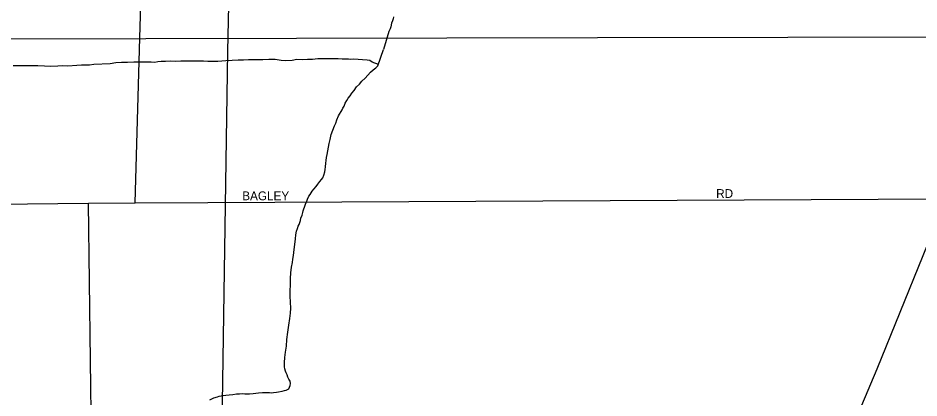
# Model space of a CAD drawing. Extents: x 2010165 to 2382125, y 1060529 to 1407316.
# Drawn here: x 2126446 to 2131582, y 1228053 to 1230221 of the extents above; entities that cross this region are included whole.
import ezdxf

# ---------------------------------------------------------------- set-up
doc = ezdxf.new("R2010")
doc.units = 0
for name, color, linetype in [('GM_X_City_Street', 7, 'Continuous'), ('GM_X_City_Street_Text', 7, 'Continuous'), ('GM_X_Corporation', 7, 'Continuous'), ('GM_X_County_Road', 7, 'Continuous'), ('GM_X_Minor_River', 7, 'Continuous'), ('GM_X_Rail_Line', 7, 'Continuous'), ('GM_X_Township_Subdivision', 7, 'Continuous')]:
    doc.layers.add(name, color=color, linetype=linetype)

msp = doc.modelspace()

# ---------------------------------------------------------------- linework, layer by layer
at = {"layer": 'GM_X_City_Street'}
for points in [[(2127528.7, 1229168.7), (2131731.9, 1229190.2)], [(2131133.5, 1227718.6), (2131344.2, 1228219.6), (2131737.3, 1229190.2)]]:
    msp.add_lwpolyline(points, dxfattribs=at)
at = {"layer": 'GM_X_Corporation'}
msp.add_lwpolyline([(2131636.8, 1226885.6), (2131550.4, 1226943.1), (2131486.1, 1226996.8), (2131429.8, 1227048.5), (2131401.6, 1227074.4), (2131379.2, 1227134.4), (2131352.4, 1227258.4), (2131342.1, 1227310.5), (2131343.7, 1227374.6), (2131363.2, 1227453), (2131396.7, 1227523.3), (2131430.3, 1227587.7), (2131468, 1227632.1), (2131573.5, 1227709), (2127608.1, 1227775.4), (2127641.5, 1230030.5), (2127699.3, 1232671.6), (2128286.9, 1232638.9), (2128858.2, 1232617.9), (2130176.4, 1232600.5), (2130656, 1232568.1), (2130665.6, 1232672.5), (2131903.1, 1232704.3)], dxfattribs=at)
at = {"layer": 'GM_X_County_Road'}
for points in [[(2127141, 1230108), (2127168.7, 1231058), (2127179.2, 1231416.5), (2127217.3, 1232723)], [(2127113.5, 1229166.6), (2127141, 1230108), (2127141, 1230108)], [(2121105.1, 1229101.1), (2126848.1, 1229163.7), (2127113.5, 1229166.6), (2127528.7, 1229168.7)]]:
    msp.add_lwpolyline(points, dxfattribs=at)
at = {"layer": 'GM_X_Minor_River'}
for points in [[(2128587.4, 1230227.7), (2128585.4, 1230215.6), (2128581.4, 1230205.6), (2128575.5, 1230191.6), (2128571.5, 1230171.5), (2128567.5, 1230159.4), (2128559.6, 1230143.3), (2128529, 1230040.7)], [(2128320.3, 1229751.1), (2128328.2, 1229763.2), (2128340, 1229777.4), (2128349.8, 1229791.6), (2128361.6, 1229807.9), (2128375.3, 1229828.1), (2128393.1, 1229844.4), (2128406.9, 1229860.7), (2128424.8, 1229877), (2128440.5, 1229895.3), (2128456.3, 1229911.6), (2128470.2, 1229925.8), (2128486.1, 1229936.1), (2128497.9, 1229948.3), (2128529, 1230040.7)], [(2128500.2, 1229955.1), (2128465.5, 1229969.9), (2128451.4, 1229977.8), (2128437.3, 1229979.5), (2128359, 1229986.4), (2128343, 1229984.2), (2128330.9, 1229986), (2128318.9, 1229985.8), (2128294.8, 1229985.5), (2128270.8, 1229987.1), (2128242.7, 1229988.8), (2128212.6, 1229988.3), (2128184.5, 1229987.9), (2128154.4, 1229987.5), (2128124.4, 1229985), (2128096.3, 1229984.6), (2128068.3, 1229982.2), (2128036.2, 1229983.7), (2128008.2, 1229979.3), (2127972.1, 1229976.8), (2127946, 1229978.4), (2127911.9, 1229983.9), (2127875.8, 1229983.4), (2127841.7, 1229982.9), (2127813.6, 1229982.5), (2127787.6, 1229982.1), (2127759.5, 1229981.7), (2127731.4, 1229981.3), (2127701.4, 1229980.8), (2127667.3, 1229978.3), (2127631.2, 1229975.8), (2127585.2, 1229973.1), (2127555.1, 1229972.7), (2127529, 1229972.3), (2127502.9, 1229973.9), (2127474.8, 1229975.5), (2127442.8, 1229975.1), (2127406.7, 1229974.5), (2127374.6, 1229974.1), (2127344.5, 1229973.6), (2127314.4, 1229975.2), (2127286.4, 1229972.8), (2127262.3, 1229972.4), (2127242.3, 1229970.1), (2127226.3, 1229967.9), (2127204.2, 1229969.6), (2127176.1, 1229969.2), (2127142.1, 1229968.7), (2127106, 1229968.1), (2127069.9, 1229967.6), (2127035.8, 1229967.1), (2127003.8, 1229964.6), (2126971.7, 1229960.2), (2126877.6, 1229954.8), (2126853.5, 1229952.4), (2126831.5, 1229952.1), (2126807.4, 1229951.8), (2126781.4, 1229949.4), (2126729.3, 1229946.6), (2126701.2, 1229948.2), (2126673.2, 1229945.8), (2126631.1, 1229945.2), (2126597, 1229946.7), (2126558.8, 1229948.1), (2126522.7, 1229947.6), (2126418.5, 1229948.1)], [(2127648.9, 1228071.7), (2127670.9, 1228074), (2127690.9, 1228076.3), (2127709, 1228076.6), (2127725, 1228078.8), (2127739, 1228077), (2127765.1, 1228077.4), (2127787.1, 1228079.7), (2127817.2, 1228082.2), (2127839.2, 1228084.5), (2127859.2, 1228084.8), (2127879.3, 1228085.1), (2127889.3, 1228083.2), (2127903.3, 1228085.4), (2127919.4, 1228085.6), (2127931.4, 1228087.8), (2127951.4, 1228092.1), (2127965.4, 1228096.4), (2127975.4, 1228098.5), (2127989.3, 1228104.7), (2127993.2, 1228114.8), (2127997, 1228124.9), (2127998.9, 1228135), (2127996.7, 1228149), (2127990.5, 1228160.9), (2127984.3, 1228172.9), (2127980.1, 1228184.9), (2127973.9, 1228196.8), (2127971.8, 1228206.8), (2127967.6, 1228218.8), (2127965.4, 1228230.8), (2127965.1, 1228254.9), (2127966.6, 1228285), (2127970.2, 1228315.2), (2127975.7, 1228349.4), (2127979.2, 1228387.5), (2127984.6, 1228427.8), (2127990, 1228468), (2127995.5, 1228506.2), (2127999.1, 1228536.3), (2128000.6, 1228566.4), (2128000.1, 1228600.6), (2127997.6, 1228634.6), (2127997.2, 1228664.7), (2127998.7, 1228698.9), (2128000.2, 1228735), (2128001.7, 1228767.1), (2128005.3, 1228799.3), (2128010.9, 1228825.5), (2128012.6, 1228845.6), (2128016.3, 1228865.7), (2128018.1, 1228883.8), (2128027, 1228960.2), (2128030.7, 1228984.3), (2128034.4, 1229004.4), (2128040.2, 1229020.6), (2128044, 1229032.6), (2128047.9, 1229042.7), (2128051.7, 1229054.8), (2128055.6, 1229064.9), (2128057.4, 1229079), (2128065.1, 1229095.2), (2128068.9, 1229111.3), (2128070.8, 1229121.3), (2128074.6, 1229131.4), (2128078.5, 1229141.5), (2128084.3, 1229159.7), (2128092, 1229175.8), (2128095.9, 1229187.9), (2128103.7, 1229204.1), (2128111.5, 1229214.2), (2128123.3, 1229232.5), (2128133.2, 1229244.6), (2128145, 1229258.9), (2128154.8, 1229273.1), (2128166.6, 1229287.3), (2128176.5, 1229299.5), (2128184.3, 1229309.6), (2128190.2, 1229323.8), (2128195.9, 1229343.9), (2128197.7, 1229356), (2128199.5, 1229372), (2128201.2, 1229392.1), (2128203, 1229408.2), (2128204.7, 1229424.3), (2128208.5, 1229442.4), (2128212.2, 1229462.5), (2128215.9, 1229484.7), (2128219.6, 1229504.8), (2128225.3, 1229526.9), (2128230.9, 1229557.1), (2128240.6, 1229581.3), (2128250.2, 1229605.6), (2128258, 1229621.7), (2128263.8, 1229639.9), (2128273.5, 1229662.1), (2128293, 1229696.5), (2128296.9, 1229706.6), (2128304.7, 1229718.7), (2128310.5, 1229734.9), (2128320.3, 1229751.1)], [(2127539, 1228042), (2127562.9, 1228054.4), (2127582.9, 1228060.7), (2127592.9, 1228062.8), (2127614.9, 1228067.2), (2127630.9, 1228069.4), (2127648.9, 1228071.7)]]:
    msp.add_lwpolyline(points, dxfattribs=at)
at = {"layer": 'GM_X_Rail_Line'}
msp.add_lwpolyline([(2113868.1, 1230085.9), (2119251.5, 1230091.7), (2120849.1, 1230095.5), (2121828.5, 1230096.3), (2123632.9, 1230100.4), (2125920.1, 1230102.1), (2127174.2, 1230104.5), (2129750.1, 1230110.3), (2131919.6, 1230114.4)], dxfattribs=at)
at = {"layer": 'GM_X_Township_Subdivision'}
msp.add_lwpolyline([(2126870.8, 1227369.4), (2126848.1, 1229163.7)], dxfattribs=at)

# ---------------------------------------------------------------- texts
at = {"layer": 'GM_X_City_Street_Text'}
for s, p in [('BAGLEY', (2127724.3, 1229181.4)), ('RD', (2130425.9, 1229194.6))]:
    msp.add_text(s, height=50, rotation=0, dxfattribs=at).set_placement(p)

doc.saveas('drawing.dxf')
